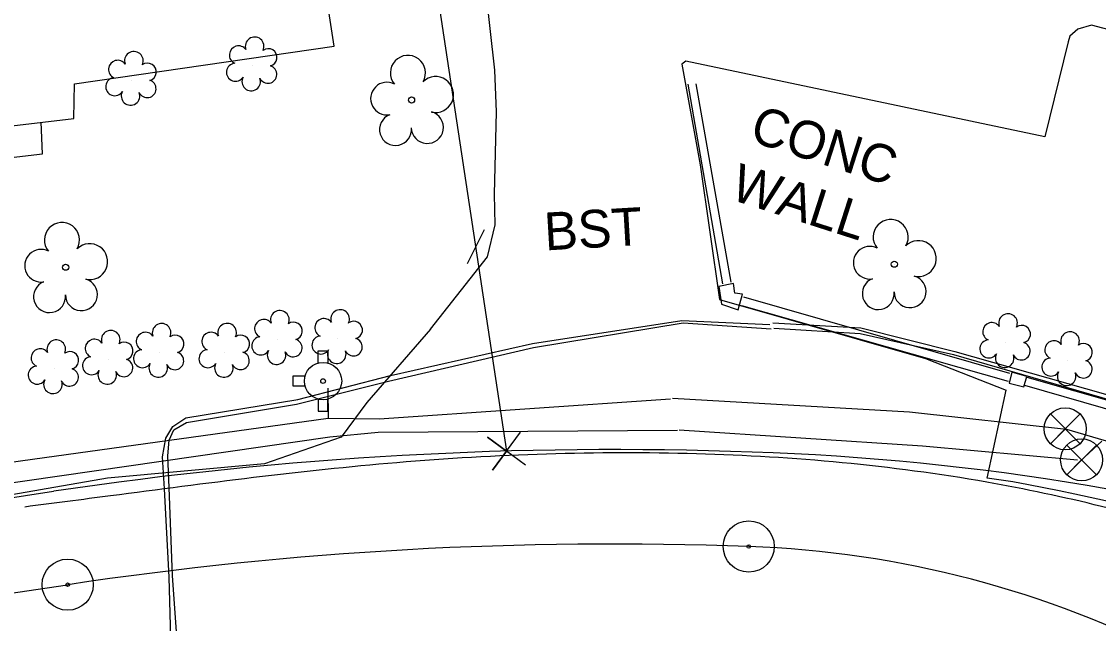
# Model space of a CAD drawing. Extents: x 553786 to 558838, y 502329 to 507342.
# Drawn here: x 557683.5 to 557797.6, y 506992.2 to 507056 of the extents above; entities that cross this region are included whole.
import ezdxf

# ---------------------------------------------------------------- set-up
doc = ezdxf.new("R2010")
doc.units = 0
for name, color, linetype in [('Exist Building Text', 7, 'Continuous'), ('Exist Hydrographic Top of Bank', 7, 'Continuous'), ('Exist Roads EOP Text', 7, 'Continuous'), ('Exist Vegetation Shrub CELL', 7, 'Continuous'), ('Exist Vegetation Tree CELL', 7, 'Continuous'), ('Prop CMT DNC', 7, 'Continuous'), ('Prop CMT Slope Grass', 7, 'Continuous'), ('Prop Drainage Structure Catch Basin Grate 840 03E Label', 7, 'Continuous'), ('Prop Drainage Structure Drop Inlet Grate 2 Wide Slots and Sag Grates 840 22 CELL', 7, 'Continuous'), ('Prop Drainage Structure Headwall CELL', 7, 'Continuous'), ('Prop Drainage Structure Junction Box with Manhole Label', 7, 'Continuous'), ('Prop Drainage Structure Pipe Alternate 24in', 7, 'Continuous'), ('Prop Drainage Structure Pipe Alternate 36in', 7, 'Continuous'), ('Prop Drainage Structure Pipe RCP 15in Class III Label', 7, 'Continuous'), ('Prop Drainage Structure Plot Symbol 50 Scale', 7, 'Continuous'), ('Prop Earthen Structure Tail Ditch Label', 7, 'Continuous'), ('Prop Erosion Rip Rap Pad at Outlet Label', 7, 'Continuous'), ('Prop Erosion Rip Rap Pad Outlet for Jurisdictional Stream CELL', 7, 'Continuous'), ('Prop Geopak Pavement Shape Independent', 7, 'Continuous'), ('Prop XS SE Text', 7, 'Continuous'), ('Sheet Layout Plan Border', 7, 'Continuous')]:
    doc.layers.add(name, color=color, linetype=linetype)

# ---------------------------------------------------------------- blocks, each defined once
blk = doc.blocks.new('EXIST UTILITIES WATER VALVE')
at = {"layer": 'Prop Drainage Structure Drop Inlet Grate 2 Wide Slots and Sag Grates 840 22 CELL'}
blk.add_lwpolyline([(0.0315, 0.0315), (-0.0315, -0.0315), (0, 0), (0.0315, -0.0315), (-0.0315, 0.0315)], dxfattribs=at)
blk.add_circle((0, 0), 0.0445, dxfattribs=at)
blk = doc.blocks.new('EXIST UTILITIES WATER FIRE HYDRANT')
at = {"layer": 'Prop Drainage Structure Junction Box with Manhole Label'}
blk.add_line((0, 0), (0, 0), dxfattribs=at)
for points in [[(-0.01025, 0.03825), (-0.01025, 0.064), (0.01025, 0.064), (0.01025, 0.03775)], [(-0.03825, 0.01025), (-0.064, 0.01025), (-0.064, -0.01025), (-0.03825, -0.01025)], [(-0.01025, -0.03825), (-0.01025, -0.064), (0.01025, -0.064), (0.01025, -0.03775)]]:
    blk.add_lwpolyline(points, dxfattribs=at)
for radius in [0.03954, 0.00485]:
    blk.add_circle((0, 0), radius, dxfattribs=at)
blk = doc.blocks.new('EXIST SURVEY CENTERLINE POINT')
at = {"layer": 'Prop Drainage Structure Catch Basin Grate 840 03E Label'}
for radius in [0.0542, 0.00375]:
    blk.add_circle((0, 0), radius, dxfattribs=at)

msp = doc.modelspace()

# ---------------------------------------------------------------- linework, layer by layer
at = {"layer": 'Exist Hydrographic Top of Bank'}
for points in [[(557585.69, 506963.98), (557586.69, 506962.61), (557588.82, 506962.76), (557593.58, 506963.53), (557601.8, 506965), (557626.13, 506968.35), (557651.81, 506971.62), (557675.66, 506975.1), (557690, 506978.01), (557699.99, 506979.54), (557700.47, 506981.22), (557700.25, 506986.07), (557700.12, 506989.35), (557699.54, 506997.23), (557699.19, 507006.58), (557699.03, 507009.95), (557699.18, 507011.62), (557699.69, 507012.72), (557701.03, 507013.49), (557712.68, 507015.41), (557722.41, 507017.86), (557737.8, 507021.41), (557753.65, 507024.04), (557762.96, 507023.4)], [(557763.25, 507023.49), (557772.4, 507022.91), (557782.28, 507020.69), (557803.97, 507014.41), (557816.06, 507010.95), (557833.19, 507003.56), (557846.77, 506995.65), (557856.52, 506988.83)]]:
    msp.add_lwpolyline(points, dxfattribs=at)
at = {"layer": 'Exist Vegetation Shrub CELL'}
for p, q in [((557708.01, 507051.28), (557708.01, 507051.28)), ((557695.22, 507049.75), (557695.22, 507049.75)), ((557717.07, 507022.4), (557717.07, 507022.4)), ((557710.69, 507022.31), (557710.69, 507022.31)), ((557787.84, 507021.97), (557787.84, 507021.97)), ((557692.76, 507020.2), (557692.76, 507020.2)), ((557698.16, 507020.94), (557698.16, 507020.94)), ((557705.1, 507020.94), (557705.1, 507020.94)), ((557687, 507019.2), (557687, 507019.2)), ((557794.4, 507020.06), (557794.4, 507020.06))]:
    msp.add_line(p, q, dxfattribs=at)
for centre, radius, start, end in [((557708.24, 507053.32), 0.99, 334.8391, 200.4717), ((557706.53, 507052.41), 0.968, 35.8908, 245.4216), ((557695.45, 507051.79), 0.99, 334.8391, 200.4717), ((557709.68, 507052.15), 0.929, 284.4567, 126.0861), ((557693.74, 507050.88), 0.968, 35.8908, 245.4216), ((557696.89, 507050.62), 0.929, 284.4567, 126.0861), ((557706.21, 507050.58), 0.955, 95.1099, 327.9534), ((557709.65, 507050.35), 0.937, 204.9913, 73.4601), ((557693.42, 507049.05), 0.955, 95.1099, 327.9534), ((557707.88, 507049.6), 0.984, 151.2797, 21.387), ((557696.86, 507048.83), 0.937, 204.9913, 73.4601), ((557695.09, 507048.07), 0.984, 151.2797, 21.387), ((557710.92, 507024.35), 0.99, 334.8391, 200.4717), ((557717.3, 507024.44), 0.99, 334.8391, 200.4717), ((557788.06, 507024.01), 0.99, 334.8391, 200.4717), ((557698.39, 507022.98), 0.99, 334.8391, 200.4717), ((557705.33, 507022.99), 0.99, 334.8391, 200.4717), ((557709.21, 507023.43), 0.968, 35.8908, 245.4216), ((557712.36, 507023.18), 0.929, 284.4567, 126.0861), ((557715.59, 507023.52), 0.968, 35.8908, 245.4216), ((557718.74, 507023.27), 0.929, 284.4567, 126.0861), ((557786.35, 507023.1), 0.968, 35.8908, 245.4216), ((557789.51, 507022.84), 0.929, 284.4567, 126.0861), ((557692.99, 507022.24), 0.99, 334.8391, 200.4717), ((557696.67, 507022.07), 0.968, 35.8908, 245.4216), ((557699.83, 507021.81), 0.929, 284.4567, 126.0861), ((557703.62, 507022.07), 0.968, 35.8908, 245.4216), ((557706.78, 507021.81), 0.929, 284.4567, 126.0861), ((557708.89, 507021.6), 0.955, 95.1099, 327.9534), ((557715.27, 507021.69), 0.955, 95.1099, 327.9534), ((557718.71, 507021.47), 0.937, 204.9913, 73.4601), ((557794.63, 507022.1), 0.99, 334.8391, 200.4717), ((557685.52, 507020.33), 0.968, 35.8908, 245.4216), ((557687.23, 507021.24), 0.99, 334.8391, 200.4717), ((557691.27, 507021.33), 0.968, 35.8908, 245.4216), ((557694.43, 507021.07), 0.929, 284.4567, 126.0861), ((557712.33, 507021.38), 0.937, 204.9913, 73.4601), ((557786.03, 507021.27), 0.955, 95.1099, 327.9534), ((557789.47, 507021.04), 0.937, 204.9913, 73.4601), ((557792.92, 507021.18), 0.968, 35.8908, 245.4216), ((557796.07, 507020.92), 0.929, 284.4567, 126.0861), ((557688.67, 507020.07), 0.929, 284.4567, 126.0861), ((557690.96, 507019.49), 0.955, 95.1099, 327.9534), ((557694.39, 507019.27), 0.937, 204.9913, 73.4601), ((557696.36, 507020.24), 0.955, 95.1099, 327.9534), ((557699.79, 507020.01), 0.937, 204.9913, 73.4601), ((557703.3, 507020.24), 0.955, 95.1099, 327.9534), ((557706.74, 507020.02), 0.937, 204.9913, 73.4601), ((557710.56, 507020.62), 0.984, 151.2797, 21.387), ((557716.94, 507020.71), 0.984, 151.2797, 21.387), ((557787.71, 507020.29), 0.984, 151.2797, 21.387), ((557792.6, 507019.35), 0.955, 95.1099, 327.9534), ((557685.2, 507018.5), 0.955, 95.1099, 327.9534), ((557688.64, 507018.27), 0.937, 204.9913, 73.4601), ((557692.63, 507018.52), 0.984, 151.2797, 21.387), ((557698.03, 507019.26), 0.984, 151.2797, 21.387), ((557704.98, 507019.26), 0.984, 151.2797, 21.387), ((557796.04, 507019.13), 0.937, 204.9913, 73.4601), ((557686.87, 507017.52), 0.984, 151.2797, 21.387), ((557794.27, 507018.37), 0.984, 151.2797, 21.387)]:
    msp.add_arc(centre, radius, start, end, dxfattribs=at)
at = {"layer": 'Exist Vegetation Tree CELL'}
for p, q in [((557724.87, 507047.64), (557724.87, 507047.64)), ((557688.22, 507029.93), (557688.22, 507029.93)), ((557776.01, 507030.25), (557776.01, 507030.25))]:
    msp.add_line(p, q, dxfattribs=at)
for centre in [(557724.87, 507047.64), (557776.01, 507030.25), (557688.22, 507029.93)]:
    msp.add_circle(centre, 0.326, dxfattribs=at)
for centre, radius, start, end in [((557724.48, 507050.51), 1.86, 330.1651, 219.7134), ((557727.42, 507048.22), 1.9, 257.1011, 134.1999), ((557722.26, 507047.79), 1.73, 62.6636, 279.3457), ((557726.54, 507044.74), 1.7, 181.2822, 74.56), ((557723.17, 507044.51), 1.69, 111.5671, 6.231), ((557775.63, 507033.12), 1.86, 330.1651, 219.7134), ((557687.83, 507032.81), 1.86, 330.1651, 219.7134), ((557778.56, 507030.84), 1.9, 257.1011, 134.1999), ((557685.61, 507030.09), 1.73, 62.6636, 279.3457), ((557690.77, 507030.52), 1.9, 257.1011, 134.1999), ((557773.41, 507030.41), 1.73, 62.6636, 279.3457), ((557686.51, 507026.81), 1.69, 111.5671, 6.231), ((557689.89, 507027.03), 1.7, 181.2822, 74.56), ((557774.31, 507027.13), 1.69, 111.5671, 6.231), ((557777.68, 507027.35), 1.7, 181.2822, 74.56)]:
    msp.add_arc(centre, radius, start, end, dxfattribs=at)
at = {"layer": 'Prop CMT DNC'}
msp.add_line((557734.91, 507010.45), (557734.91, 507010.45), dxfattribs=at)
msp.add_lwpolyline([(557736.93, 507008.97), (557732.9, 507011.93), (557734.91, 507010.45), (557733.43, 507008.44), (557736.4, 507012.46)], dxfattribs=at)
at = {"layer": 'Prop CMT Slope Grass'}
msp.add_line((557730.8, 507030.32), (557732.61, 507033.93), dxfattribs=at)
at = {"layer": 'Prop Drainage Structure Headwall CELL'}
msp.add_spline([(557900.73, 506947.77), (557877.79, 506965.61), (557850.98, 506982.42), (557839.36, 506989.04), (557809.92, 507001.23), (557785.8, 507007.16), (557755.06, 507010.16), (557723.31, 507009.22), (557692.97, 507005.71), (557683.89, 507004.53)], degree=3, dxfattribs=at)
at = {"layer": 'Prop Drainage Structure Pipe Alternate 24in'}
msp.add_line((557796.21, 507009.85), (557798.01, 507011.52), dxfattribs=at)
for points in [[(557715.99, 507017.12), (557716.03, 507013.94)], [(557716.03, 507013.94), (557721.42, 507013.87), (557752.29, 507015.98)], [(557752.53, 507016.05), (557777.63, 507014.61), (557794.27, 507012.76), (557798.21, 507011.62), (557805.95, 507009.56), (557812.22, 507008.44), (557828.88, 507004.28), (557838.32, 506999.04), (557845.4, 506993.72)], [(557639.69, 507003.15), (557679.82, 507008.91), (557716.03, 507013.94)], [(557640.42, 507000.89), (557680.43, 507006.8), (557716.2, 507011.95), (557721.32, 507012.45), (557753.05, 507012.66)], [(557753.23, 507012.71), (557778.99, 507011.02), (557795.41, 507009.54)]]:
    msp.add_lwpolyline(points, dxfattribs=at)
at = {"layer": 'Prop Drainage Structure Pipe Alternate 36in'}
for points in [[(557726.88, 507023.38), (557720.14, 507015.61), (557717.41, 507011.93), (557709.28, 507009.12), (557692.64, 507007.59), (557664.23, 507002.65), (557643.84, 506999.35)], [(557788.58, 507007.21), (557785.86, 507007.6), (557787.86, 507016.91)]]:
    msp.add_lwpolyline(points, dxfattribs=at)
msp.add_ellipse((557725.29, 506677.77), major_axis=(-317.09, 111.18), ratio=0.998323, start_param=4.700556, end_param=4.859587, dxfattribs=at)
at = {"layer": 'Prop Drainage Structure Pipe RCP 15in Class III Label'}
msp.add_line((557304.39, 506948.91), (557686.95, 507006.19), dxfattribs=at)
for centre, radius, start, end in [((557746.29, 506609.96), 400.65, 87.9014, 98.5167), ((557752.44, 506745.03), 265.45, 57.4224, 88.1615)]:
    msp.add_arc(centre, radius, start, end, dxfattribs=at)
at = {"layer": 'Prop Drainage Structure Plot Symbol 50 Scale'}
for points in [[(557726.88, 507023.38), (557732.93, 507031.02), (557733.74, 507034.41), (557733.66, 507037.67), (557733.88, 507046.39), (557733.7, 507050.79), (557731.78, 507067.84), (557730.67, 507085.18), (557729.97, 507095.56), (557728.41, 507115.31), (557726.63, 507133.75), (557726.09, 507143.07), (557725.9, 507146.33)], [(557815.29, 507050.69), (557796.92, 507055.55), (557795.47, 507055.15), (557794.6, 507054.39), (557794.43, 507053.81), (557791.97, 507043.74), (557753.92, 507051.75), (557753.5, 507051.44), (557755.43, 507040.78), (557757.49, 507026.51), (557779.32, 507020.25), (557787.86, 507016.91)]]:
    msp.add_lwpolyline(points, dxfattribs=at)
at = {"layer": 'Prop Earthen Structure Tail Ditch Label'}
msp.add_lwpolyline([(557625.15, 507032.78), (557639.02, 507035.91), (557657.97, 507038.68), (557685.77, 507041.95), (557685.61, 507045.28)], dxfattribs=at)
at = {"layer": 'Prop Erosion Rip Rap Pad at Outlet Label'}
for points in [[(557601.85, 506965.79), (557626.21, 506968.8), (557651.59, 506972), (557675.63, 506975.9), (557689.91, 506978.33), (557695.38, 506979.48), (557697.69, 506980.53), (557699.12, 506982.16), (557699.76, 506985.59), (557699.39, 506989.4), (557699.17, 506997.11), (557698.7, 507006.47), (557698.48, 507009.84), (557698.82, 507011.81), (557699.58, 507013.05), (557700.96, 507013.99), (557712.82, 507015.92), (557722.62, 507018.47), (557737.68, 507021.84), (557753.49, 507024.29), (557762.82, 507023.87)], [(557763.16, 507024.05), (557772.48, 507023.51), (557782.42, 507021.01), (557804.26, 507014.84), (557816.21, 507011.33), (557833.5, 507004.01), (557847.23, 506996.05), (557856.88, 506989.2)]]:
    msp.add_lwpolyline(points, dxfattribs=at)
at = {"layer": 'Prop Erosion Rip Rap Pad Outlet for Jurisdictional Stream CELL'}
for p, q in [((557754.15, 507049.33), (557757.8, 507028.18)), ((557755, 507049.36), (557758.71, 507028.36)), ((557759.84, 507025.86), (557788.08, 507017.85)), ((557760.05, 507026.79), (557788.2, 507018.72)), ((557790.07, 507018.29), (557818.46, 507010.18)), ((557789.79, 507017.42), (557818.21, 507009.26))]:
    msp.add_line(p, q, dxfattribs=at)
msp.add_lwpolyline([(557639.07, 507044.85), (557661.77, 507047.93), (557662.18, 507042.49), (557689.08, 507045.69), (557689.15, 507049.37), (557716.68, 507053.35), (557711.31, 507088.25), (557684.42, 507084.2), (557682.7, 507096.62), (557662.57, 507093.99), (557663.96, 507081.47), (557659.69, 507081.18), (557660.03, 507078.78), (557635.24, 507075.85)], close=True, dxfattribs=at)
for points in [[(557757.42, 507027.9), (557757.7, 507026.01), (557759.48, 507025.43), (557759.94, 507027.06), (557759.12, 507027.18), (557758.98, 507028.19), (557757.42, 507027.9)], [(557788.18, 507017.65), (557789.72, 507017.27), (557790.07, 507018.37), (557788.45, 507018.82), (557788.18, 507017.65)]]:
    msp.add_lwpolyline(points, dxfattribs=at)
at = {"layer": 'Prop XS SE Text'}
msp.add_line((557709.54, 507178.3), (557734.91, 507010.45), dxfattribs=at)
at = {"layer": 'Sheet Layout Plan Border'}
msp.add_line((557436.99, 506958.65), (557688.43, 506996.3), dxfattribs=at)
for centre, radius, start, end in [((557746.29, 506609.96), 390.65, 87.9014, 98.5167), ((557756.61, 506891.81), 108.62, 37.7741, 87.9014)]:
    msp.add_arc(centre, radius, start, end, dxfattribs=at)

# ---------------------------------------------------------------- block references
at = {"layer": 'Prop Drainage Structure Drop Inlet Grate 2 Wide Slots and Sag Grates 840 22 CELL', "xscale": 50, "yscale": 50}
for p in [(557794.12, 507012.81), (557795.86, 507009.52)]:
    msp.add_blockref('EXIST UTILITIES WATER VALVE', p, dxfattribs=at)
at = {"layer": 'Prop Drainage Structure Junction Box with Manhole Label', "xscale": 50, "yscale": 50}
msp.add_blockref('EXIST UTILITIES WATER FIRE HYDRANT', (557715.49, 507017.87), dxfattribs=at)
at = {"layer": 'Prop Geopak Pavement Shape Independent', "xscale": 50, "yscale": 50}
for p in [(557760.59, 507000.35), (557688.43, 506996.3)]:
    msp.add_blockref('EXIST SURVEY CENTERLINE POINT', p, dxfattribs=at)

# ---------------------------------------------------------------- texts
at = {"layer": 'Exist Building Text'}
for s, p in [('CONC', (557760.52, 507043.34)), ('WALL', (557758.47, 507037.17))]:
    msp.add_text(s, height=4, rotation=342.2224, dxfattribs=at).set_placement(p)
at = {"layer": 'Exist Roads EOP Text'}
msp.add_text('BST', height=4, rotation=3.3504, dxfattribs=at).set_placement((557739.03, 507031.7))

doc.saveas('drawing.dxf')
